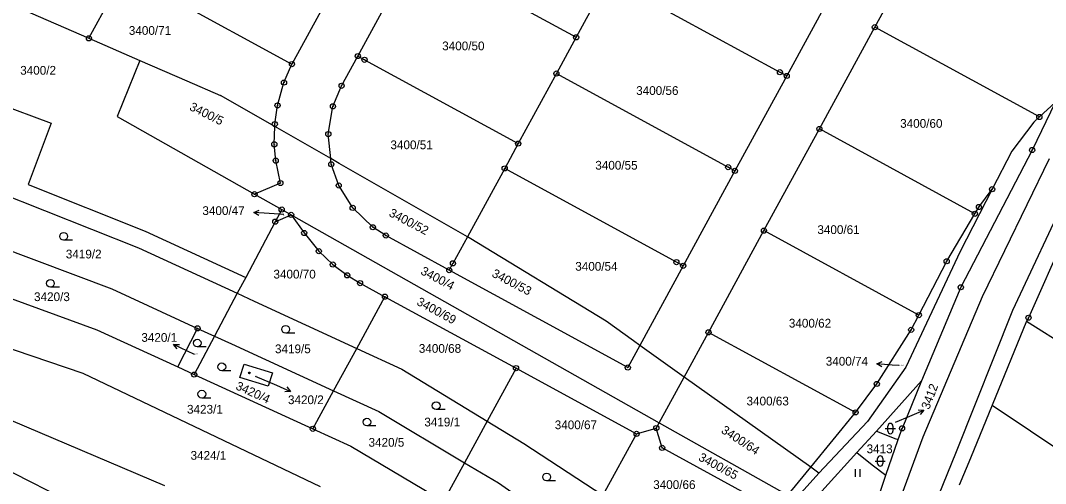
# Model space of a CAD drawing. Extents: x -593183 to -588034, y -1130415 to -1124994.
# Drawn here: x -592529.4 to -592330.3, y -1128767.8 to -1128677.9 of the extents above; entities that cross this region are included whole.
import ezdxf

# ---------------------------------------------------------------- set-up
doc = ezdxf.new("R2010")
doc.units = 0
for name, color, linetype in [('Vrstva 1', 7, 'Continuous'), ('Vrstva 16', 7, 'Continuous'), ('Vrstva 18', 7, 'Continuous'), ('Vrstva 19', 7, 'Continuous'), ('Vrstva 24', 7, 'Continuous'), ('Vrstva 25', 7, 'Continuous'), ('Vrstva 4', 7, 'Continuous')]:
    doc.layers.add(name, color=color, linetype=linetype)

msp = doc.modelspace()

# ---------------------------------------------------------------- linework, layer by layer
at = {"layer": 'Vrstva 1'}
for p, q in [((-592463.89, -1128684.8), (-592452.63, -1128664.17)), ((-592451.32, -1128664.89), (-592421.47, -1128681.16)), ((-592363.45, -1128679.2), (-592355.69, -1128664.97)), ((-592516.11, -1128681.35), (-592509.18, -1128668.65)), ((-592509.18, -1128668.65), (-592476.68, -1128686.37)), ((-592415.24, -1128669.75), (-592421.47, -1128681.16)), ((-592415.24, -1128669.75), (-592381.88, -1128687.94)), ((-592370.51, -1128670.22), (-592380.56, -1128688.66)), ((-592537.4, -1128672.05), (-592516.11, -1128681.35)), ((-592374.22, -1128698.95), (-592363.45, -1128679.2)), ((-592331.49, -1128696.63), (-592363.45, -1128679.2)), ((-592516.11, -1128681.35), (-592506.23, -1128685.64)), ((-592421.47, -1128681.16), (-592425.3, -1128688.19)), ((-592506.23, -1128685.64), (-592509.5, -1128693.81)), ((-592506.23, -1128685.64), (-592497.07, -1128689.63)), ((-592463.89, -1128684.8), (-592462.57, -1128685.52)), ((-592462.57, -1128685.52), (-592432.72, -1128701.8)), ((-592425.3, -1128688.19), (-592432.72, -1128701.8)), ((-592425.3, -1128688.19), (-592391.93, -1128706.38)), ((-592380.56, -1128688.66), (-592390.62, -1128707.1)), ((-592380.56, -1128688.66), (-592381.88, -1128687.94)), ((-592497.07, -1128689.63), (-592490.56, -1128692.47)), ((-592538.73, -1128692.12), (-592523.45, -1128697.86)), ((-592480.01, -1128698.5), (-592490.56, -1128692.47)), ((-592509.5, -1128693.81), (-592510.61, -1128696.56)), ((-592328.41, -1128693.84), (-592332.9, -1128703.05)), ((-592328.41, -1128693.84), (-592331.49, -1128696.63)), ((-592510.61, -1128696.56), (-592483.96, -1128711.63)), ((-592331.49, -1128696.63), (-592332.58, -1128697.62)), ((-592523.45, -1128697.86), (-592527.9, -1128709.77)), ((-592469.15, -1128704.72), (-592480.01, -1128698.5)), ((-592332.58, -1128697.62), (-592336.85, -1128703.28)), ((-592384.99, -1128718.71), (-592374.22, -1128698.95)), ((-592344.02, -1128715.43), (-592374.22, -1128698.95)), ((-592432.72, -1128701.8), (-592435.35, -1128706.62)), ((-592332.9, -1128703.05), (-592346.75, -1128729.7)), ((-592336.85, -1128703.28), (-592340.66, -1128710.66)), ((-592467.5, -1128705.66), (-592469.15, -1128704.72)), ((-592442.59, -1128719.9), (-592467.5, -1128705.66)), ((-592435.35, -1128706.62), (-592442.59, -1128719.9)), ((-592401.99, -1128724.82), (-592435.35, -1128706.62)), ((-592390.62, -1128707.1), (-592391.93, -1128706.38)), ((-592390.62, -1128707.1), (-592400.67, -1128725.53)), ((-592539.83, -1128708.8), (-592506.46, -1128722.05)), ((-592527.9, -1128709.77), (-592505.17, -1128718.8)), ((-592478.92, -1128709.47), (-592483.96, -1128711.63)), ((-592340.66, -1128710.66), (-592346.9, -1128722.74)), ((-592343.23, -1128714.12), (-592340.66, -1128710.66)), ((-592562.55, -1128710.89), (-592511.66, -1128730)), ((-592483.96, -1128711.63), (-592478.67, -1128714.61)), ((-592478.67, -1128714.61), (-592479.92, -1128716.97)), ((-592478.67, -1128714.61), (-592476.83, -1128715.65)), ((-592344.02, -1128715.43), (-592343.23, -1128714.12)), ((-592479.92, -1128716.97), (-592476.83, -1128715.65)), ((-592476.83, -1128715.65), (-592405.33, -1128756.01)), ((-592479.92, -1128716.97), (-592485.65, -1128727.79)), ((-592567.7, -1128718.67), (-592514.6, -1128737.95)), ((-592505.17, -1128718.8), (-592485.65, -1128727.79)), ((-592442.59, -1128719.9), (-592445.4, -1128725.06)), ((-592442.26, -1128720.09), (-592442.59, -1128719.9)), ((-592415.67, -1128736.3), (-592442.26, -1128720.09)), ((-592395.76, -1128738.46), (-592384.99, -1128718.71)), ((-592354.91, -1128735.11), (-592384.99, -1128718.71)), ((-592326.42, -1128719.46), (-592333.6, -1128735.62)), ((-592506.46, -1128722.05), (-592487.29, -1128730.87)), ((-592346.9, -1128722.74), (-592357.41, -1128745.24)), ((-592446.12, -1128726.38), (-592445.4, -1128725.06)), ((-592411.44, -1128745.29), (-592446.12, -1128726.38)), ((-592400.67, -1128725.53), (-592409.1, -1128740.99)), ((-592400.67, -1128725.53), (-592401.99, -1128724.82)), ((-592573.65, -1128727.2), (-592517.32, -1128746.38)), ((-592485.65, -1128727.79), (-592487.29, -1128730.87)), ((-592511.66, -1128730), (-592495, -1128737.68)), ((-592346.75, -1128729.7), (-592354.39, -1128747.86)), ((-592487.29, -1128730.87), (-592491.7, -1128739.2)), ((-592487.29, -1128730.87), (-592483.99, -1128732.38)), ((-592483.99, -1128732.38), (-592464.09, -1128741.57)), ((-592464.09, -1128741.57), (-592458.61, -1128731.53)), ((-592458.61, -1128731.53), (-592433.15, -1128745.41)), ((-592410.33, -1128740.11), (-592415.67, -1128736.3)), ((-592333.99, -1128736.29), (-592340.66, -1128752.59)), ((-592333.6, -1128735.62), (-592333.99, -1128736.29)), ((-592333.99, -1128736.29), (-592315.35, -1128748.08)), ((-592514.6, -1128737.95), (-592498.87, -1128745.18)), ((-592498.87, -1128745.18), (-592495, -1128737.68)), ((-592495, -1128737.68), (-592491.7, -1128739.2)), ((-592400.49, -1128747.13), (-592395.76, -1128738.46)), ((-592367.18, -1128754), (-592395.76, -1128738.46)), ((-592491.7, -1128739.2), (-592495.66, -1128746.66)), ((-592491.7, -1128739.2), (-592488.4, -1128740.7)), ((-592409.1, -1128740.99), (-592410.33, -1128740.11)), ((-592488.4, -1128740.7), (-592468.59, -1128749.82)), ((-592468.59, -1128749.82), (-592464.09, -1128741.57)), ((-592464.09, -1128741.57), (-592455.3, -1128745.62)), ((-592409.1, -1128740.99), (-592411.44, -1128745.29)), ((-592400.49, -1128747.13), (-592409.1, -1128740.99)), ((-592517.32, -1128746.38), (-592471.18, -1128768.42)), ((-592498.87, -1128745.18), (-592495.66, -1128746.66)), ((-592486.78, -1128747.21), (-592485.97, -1128744.61)), ((-592485.97, -1128744.61), (-592480.48, -1128746.32)), ((-592480.48, -1128746.32), (-592481.29, -1128748.92)), ((-592455.3, -1128745.62), (-592438.76, -1128755.69)), ((-592433.15, -1128745.41), (-592438.76, -1128755.69)), ((-592433.15, -1128745.41), (-592409.73, -1128758.18)), ((-592357.41, -1128745.24), (-592364.89, -1128755.79)), ((-592495.66, -1128746.66), (-592472.61, -1128757.19)), ((-592481.29, -1128748.92), (-592486.78, -1128747.21)), ((-592405.33, -1128756.01), (-592400.49, -1128747.13)), ((-592375.91, -1128764.65), (-592400.49, -1128747.13)), ((-592354.39, -1128747.86), (-592363.15, -1128757.65)), ((-592354.39, -1128747.86), (-592358.16, -1128757.1)), ((-592472.61, -1128757.19), (-592468.59, -1128749.82)), ((-592468.59, -1128749.82), (-592459.78, -1128753.86)), ((-592542.34, -1128750.84), (-592501.44, -1128768.19)), ((-592459.78, -1128753.86), (-592443.17, -1128763.78)), ((-592375.91, -1128764.65), (-592367.18, -1128754)), ((-592340.66, -1128752.59), (-592344.88, -1128762.87)), ((-592340.66, -1128752.59), (-592318.82, -1128767.24)), ((-592438.76, -1128755.69), (-592443.17, -1128763.78)), ((-592438.76, -1128755.69), (-592431.6, -1128760.04)), ((-592405.9, -1128757.05), (-592405.33, -1128756.01)), ((-592405.33, -1128756.01), (-592380.91, -1128769.78)), ((-592364.89, -1128755.79), (-592374.32, -1128765.79)), ((-592472.61, -1128757.19), (-592465.21, -1128760.57)), ((-592409.73, -1128758.18), (-592416.3, -1128770.05)), ((-592409.73, -1128758.18), (-592405.9, -1128757.05)), ((-592404.77, -1128760.89), (-592405.9, -1128757.05)), ((-592363.15, -1128757.65), (-592366.94, -1128761.82)), ((-592363.15, -1128757.65), (-592359.39, -1128759.11)), ((-592358.92, -1128759.29), (-592358.16, -1128757.1)), ((-592431.6, -1128760.04), (-592416.3, -1128770.05)), ((-592361.31, -1128766.22), (-592358.92, -1128759.29)), ((-592359.39, -1128759.11), (-592358.92, -1128759.29)), ((-592539.2, -1128761.5), (-592512.55, -1128775)), ((-592465.21, -1128760.57), (-592447.25, -1128771.27)), ((-592383.4, -1128772.54), (-592404.77, -1128760.89)), ((-592366.94, -1128761.82), (-592373.75, -1128769.33)), ((-592366.94, -1128761.82), (-592363.95, -1128764.16)), ((-592443.17, -1128763.78), (-592447.25, -1128771.27)), ((-592443.17, -1128763.78), (-592436.57, -1128767.71)), ((-592363.95, -1128764.16), (-592361.31, -1128766.22)), ((-592344.88, -1128762.87), (-592347.06, -1128768.15)), ((-592374.32, -1128765.79), (-592378.94, -1128770.89)), ((-592374.32, -1128765.79), (-592375.91, -1128764.65)), ((-592364.49, -1128775.42), (-592361.31, -1128766.22)), ((-592436.57, -1128767.71), (-592420.95, -1128778.46))]:
    msp.add_line(p, q, dxfattribs=at)
for points in [[(-592498.65, -1128649.33), (-592469.67, -1128665.13), (-592468.08, -1128670.56), (-592476.68, -1128686.37)], [(-592480.01, -1128698.5), (-592480, -1128698.01), (-592479.47, -1128694.38), (-592478.22, -1128689.95), (-592476.68, -1128686.37)], [(-592469.15, -1128704.72), (-592469.61, -1128699.96), (-592468.71, -1128694.57), (-592467.03, -1128690.58), (-592463.89, -1128684.8)], [(-592478.92, -1128709.47), (-592479.83, -1128705.11), (-592480.1, -1128701.94), (-592480.01, -1128698.5)], [(-592446.12, -1128726.38), (-592458.45, -1128719.65), (-592460.96, -1128718.05), (-592464.88, -1128714.28), (-592467.59, -1128709.94), (-592469.04, -1128705.82), (-592469.15, -1128704.72)], [(-592476.83, -1128715.65), (-592474.3, -1128719.16), (-592471.46, -1128722.69), (-592468.72, -1128725.29), (-592465.93, -1128727.38), (-592463.44, -1128728.9), (-592458.61, -1128731.53)], [(-592354.91, -1128735.11), (-592349.49, -1128724.65), (-592344.02, -1128715.43)], [(-592367.18, -1128754), (-592363.07, -1128748.48), (-592356.39, -1128737.97), (-592354.91, -1128735.11)], [(-592382.73, -1128772.9), (-592379.79, -1128769.38), (-592375.91, -1128764.65)]]:
    msp.add_lwpolyline(points, dxfattribs=at)
at = {"layer": 'Vrstva 16'}
for p, q in [((-592478.28, -1128715.55), (-592481.11, -1128715.37)), ((-592495.63, -1128742.76), (-592496.96, -1128742.11)), ((-592358.77, -1128744.91), (-592360.07, -1128744.8)), ((-592483.8, -1128746.94), (-592479.68, -1128748.73)), ((-592359.42, -1128755.93), (-592356.67, -1128754.75))]:
    msp.add_line(p, q, dxfattribs=at)
at = {"layer": 'Vrstva 24'}
for centre, radius in [((-592363.45, -1128679.2), 0.5), ((-592421.47, -1128681.16), 0.5), ((-592363.45, -1128679.2), 0.0327), ((-592516.11, -1128681.35), 0.5), ((-592516.11, -1128681.35), 0.0327), ((-592421.47, -1128681.16), 0.0327), ((-592463.89, -1128684.8), 0.5), ((-592463.89, -1128684.8), 0.0327), ((-592476.68, -1128686.37), 0.5), ((-592476.68, -1128686.37), 0.0327), ((-592462.57, -1128685.52), 0.5), ((-592462.57, -1128685.52), 0.0327), ((-592425.3, -1128688.19), 0.5), ((-592425.3, -1128688.19), 0.0327), ((-592381.88, -1128687.94), 0.5), ((-592381.88, -1128687.94), 0.0327), ((-592380.56, -1128688.66), 0.5), ((-592380.56, -1128688.66), 0.0327), ((-592478.22, -1128689.95), 0.5), ((-592478.22, -1128689.95), 0.0327), ((-592467.03, -1128690.58), 0.5), ((-592467.03, -1128690.58), 0.0327), ((-592479.47, -1128694.38), 0.5), ((-592479.47, -1128694.38), 0.0327), ((-592468.71, -1128694.57), 0.5), ((-592468.71, -1128694.57), 0.0327), ((-592331.49, -1128696.63), 0.5), ((-592331.49, -1128696.63), 0.0327), ((-592480, -1128698.01), 0.5), ((-592480, -1128698.01), 0.0327), ((-592374.22, -1128698.95), 0.5), ((-592469.61, -1128699.96), 0.5), ((-592469.61, -1128699.96), 0.0327), ((-592374.22, -1128698.95), 0.0327), ((-592480.1, -1128701.94), 0.5), ((-592480.1, -1128701.94), 0.0327), ((-592432.72, -1128701.8), 0.5), ((-592432.72, -1128701.8), 0.0327), ((-592332.9, -1128703.05), 0.5), ((-592479.83, -1128705.11), 0.5), ((-592332.9, -1128703.05), 0.0327), ((-592479.83, -1128705.11), 0.0327), ((-592469.04, -1128705.82), 0.5), ((-592469.04, -1128705.82), 0.0327), ((-592435.35, -1128706.62), 0.5), ((-592435.35, -1128706.62), 0.0327), ((-592391.93, -1128706.38), 0.5), ((-592391.93, -1128706.38), 0.0327), ((-592390.62, -1128707.1), 0.5), ((-592390.62, -1128707.1), 0.0327), ((-592478.92, -1128709.47), 0.5), ((-592478.92, -1128709.47), 0.0327), ((-592467.59, -1128709.94), 0.5), ((-592467.59, -1128709.94), 0.0327), ((-592340.66, -1128710.66), 0.5), ((-592340.66, -1128710.66), 0.0327), ((-592483.96, -1128711.63), 0.5), ((-592483.96, -1128711.63), 0.0327), ((-592478.67, -1128714.61), 0.5), ((-592478.67, -1128714.61), 0.0327), ((-592464.88, -1128714.28), 0.5), ((-592464.88, -1128714.28), 0.0327), ((-592343.23, -1128714.12), 0.5), ((-592343.23, -1128714.12), 0.0327), ((-592479.92, -1128716.97), 0.5), ((-592476.83, -1128715.65), 0.5), ((-592476.83, -1128715.65), 0.0327), ((-592344.02, -1128715.43), 0.5), ((-592344.02, -1128715.43), 0.0327), ((-592479.92, -1128716.97), 0.0327), ((-592460.96, -1128718.05), 0.5), ((-592460.96, -1128718.05), 0.0327), ((-592384.99, -1128718.71), 0.5), ((-592474.3, -1128719.16), 0.5), ((-592474.3, -1128719.16), 0.0327), ((-592458.45, -1128719.65), 0.5), ((-592458.45, -1128719.65), 0.0327), ((-592384.99, -1128718.71), 0.0327), ((-592471.46, -1128722.69), 0.5), ((-592471.46, -1128722.69), 0.0327), ((-592445.4, -1128725.06), 0.5), ((-592401.99, -1128724.82), 0.5), ((-592349.49, -1128724.65), 0.5), ((-592468.72, -1128725.29), 0.5), ((-592468.72, -1128725.29), 0.0327), ((-592446.12, -1128726.38), 0.5), ((-592446.12, -1128726.38), 0.0327), ((-592445.4, -1128725.06), 0.0327), ((-592401.99, -1128724.82), 0.0327), ((-592400.67, -1128725.53), 0.5), ((-592400.67, -1128725.53), 0.0327), ((-592349.49, -1128724.65), 0.0327), ((-592465.93, -1128727.38), 0.5), ((-592465.93, -1128727.38), 0.0327), ((-592463.44, -1128728.9), 0.5), ((-592463.44, -1128728.9), 0.0327), ((-592346.75, -1128729.7), 0.5), ((-592346.75, -1128729.7), 0.0327), ((-592458.61, -1128731.53), 0.5), ((-592458.61, -1128731.53), 0.0327), ((-592354.91, -1128735.11), 0.5), ((-592354.91, -1128735.11), 0.0327), ((-592333.6, -1128735.62), 0.5), ((-592333.6, -1128735.62), 0.0327), ((-592495, -1128737.68), 0.5), ((-592495, -1128737.68), 0.0327), ((-592395.76, -1128738.46), 0.5), ((-592395.76, -1128738.46), 0.0327), ((-592356.39, -1128737.97), 0.5), ((-592356.39, -1128737.97), 0.0327), ((-592495.66, -1128746.66), 0.5), ((-592433.15, -1128745.41), 0.5), ((-592433.15, -1128745.41), 0.0327), ((-592411.44, -1128745.29), 0.5), ((-592411.44, -1128745.29), 0.0327), ((-592495.66, -1128746.66), 0.0327), ((-592363.07, -1128748.48), 0.5), ((-592363.07, -1128748.48), 0.0327), ((-592367.18, -1128754), 0.5), ((-592367.18, -1128754), 0.0327), ((-592472.61, -1128757.19), 0.5), ((-592472.61, -1128757.19), 0.0327), ((-592409.73, -1128758.18), 0.5), ((-592409.73, -1128758.18), 0.0327), ((-592405.9, -1128757.05), 0.5), ((-592405.9, -1128757.05), 0.0327), ((-592358.16, -1128757.1), 0.5), ((-592358.16, -1128757.1), 0.0327), ((-592404.77, -1128760.89), 0.5), ((-592404.77, -1128760.89), 0.0327)]:
    msp.add_circle(centre, radius, dxfattribs=at)
at = {"layer": 'Vrstva 25'}
for p, q in [((-592481.11, -1128715.37), (-592484.1, -1128715.18)), ((-592519.28, -1128720.57), (-592521.03, -1128720.57)), ((-592521.84, -1128729.69), (-592523.59, -1128729.69)), ((-592476.14, -1128738.62), (-592477.89, -1128738.62)), ((-592496.96, -1128742.11), (-592499.66, -1128740.8)), ((-592493.32, -1128741.29), (-592495.07, -1128741.29)), ((-592488.55, -1128745.91), (-592490.3, -1128745.91)), ((-592360.07, -1128744.8), (-592363.06, -1128744.55)), ((-592479.68, -1128748.73), (-592476.93, -1128749.93)), ((-592492.43, -1128751.21), (-592494.18, -1128751.21)), ((-592446.91, -1128753.45), (-592448.66, -1128753.45)), ((-592356.67, -1128754.75), (-592353.91, -1128753.57)), ((-592460.36, -1128756.64), (-592462.11, -1128756.64)), ((-592361.43, -1128757.15), (-592359.43, -1128757.15)), ((-592360.93, -1128757.65), (-592360.93, -1128756.65)), ((-592359.93, -1128756.65), (-592359.93, -1128757.65)), ((-592363.41, -1128763.45), (-592361.41, -1128763.45)), ((-592362.91, -1128763.95), (-592362.91, -1128762.95)), ((-592361.91, -1128762.95), (-592361.91, -1128763.95)), ((-592367.29, -1128765.04), (-592367.29, -1128766.54)), ((-592366.27, -1128766.54), (-592366.27, -1128765.04)), ((-592425.45, -1128767.3), (-592427.2, -1128767.3))]:
    msp.add_line(p, q, dxfattribs=at)
for points in [[(-592483.14, -1128715.74), (-592484.1, -1128715.18), (-592483.07, -1128714.74)], [(-592498.98, -1128741.68), (-592499.66, -1128740.8), (-592498.54, -1128740.79)], [(-592362.11, -1128745.13), (-592363.06, -1128744.55), (-592362.02, -1128744.13)], [(-592477.65, -1128749.07), (-592476.93, -1128749.93), (-592478.05, -1128749.99)], [(-592355.03, -1128753.5), (-592353.91, -1128753.57), (-592354.63, -1128754.42)]]:
    msp.add_lwpolyline(points, dxfattribs=at)
for centre, radius in [((-592521.03, -1128719.82), 0.75), ((-592523.59, -1128728.94), 0.75), ((-592477.89, -1128737.87), 0.75), ((-592495.07, -1128740.54), 0.75), ((-592490.3, -1128745.16), 0.75), ((-592484.95, -1128746.34), 0.175), ((-592484.95, -1128746.34), 0.15), ((-592494.18, -1128750.46), 0.75), ((-592448.66, -1128752.7), 0.75), ((-592462.11, -1128755.89), 0.75), ((-592427.2, -1128766.55), 0.75)]:
    msp.add_circle(centre, radius, dxfattribs=at)
for centre, start, end in [((-592360.43, -1128756.65), 90, 180), ((-592360.43, -1128756.65), 0, 90), ((-592360.43, -1128757.65), 180, 270), ((-592360.43, -1128757.65), 270, 0), ((-592362.41, -1128762.95), 90, 180), ((-592362.41, -1128763.95), 180, 270), ((-592362.41, -1128762.95), 0, 90), ((-592362.41, -1128763.95), 270, 0)]:
    msp.add_arc(centre, 0.5, start, end, dxfattribs=at)
at = {"layer": 'Vrstva 4'}
for p, q in [((-592329.61, -1128704.73), (-592342.61, -1128731.57)), ((-592324.18, -1128707.5), (-592336.73, -1128734.21)), ((-592342.61, -1128731.57), (-592354.15, -1128758.84)), ((-592336.73, -1128734.21), (-592347.67, -1128761.66)), ((-592354.15, -1128758.84), (-592364.52, -1128786.87)), ((-592347.67, -1128761.66), (-592358.89, -1128789.2))]:
    msp.add_line(p, q, dxfattribs=at)

# ---------------------------------------------------------------- texts
at = {"layer": 'Vrstva 16'}
for s, p in [('3400/47', (-592494.07, -1128715.67)), ('3420/1', (-592505.93, -1128740.3)), ('3400/74', (-592372.98, -1128744.92)), ('3420/2', (-592477.45, -1128752.4))]:
    msp.add_text(s, height=1.7, dxfattribs=at).set_placement(p)
msp.add_text('3412', height=1.7, rotation=69.1349, dxfattribs=at).set_placement((-592352.91, -1128753.57))
at = {"layer": 'Vrstva 18'}
for s, height, p in [('3400/71', 1.7, (-592508.36, -1128680.68)), ('3400/50', 1.7, (-592447.49, -1128683.68)), ('3400/2', 1.7, (-592529.46, -1128688.42)), ('3400/56', 1.7, (-592409.81, -1128692.35)), ('3400/60', 1.7, (-592358.53, -1128698.73)), ('3400/51', 1.7, (-592457.54, -1128702.89)), ('3400/55', 1.7, (-592417.75, -1128706.86)), ('3400/47', 0.2, (-592478.75, -1128715.8)), ('3400/61', 1.7, (-592374.61, -1128719.36)), ('3419/2', 1.7, (-592520.6, -1128724.1)), ('3400/70', 1.7, (-592480.27, -1128728)), ('3400/54', 1.7, (-592421.64, -1128726.49)), ('3420/3', 1.7, (-592526.77, -1128732.39)), ('3400/62', 1.7, (-592380.15, -1128737.53)), ('3419/5', 1.7, (-592479.97, -1128742.51)), ('3400/68', 1.7, (-592452.03, -1128742.43)), ('3420/1', 0.2, (-592495.63, -1128742.76)), ('3400/74', 0.2, (-592358.77, -1128744.91)), ('3423/1', 1.7, (-592497.06, -1128754.25)), ('3400/63', 1.7, (-592388.37, -1128752.65)), ('3419/1', 1.7, (-592450.96, -1128756.73)), ('3400/67', 1.7, (-592425.63, -1128757.27)), ('3412', 0.1, (-592359.42, -1128755.93)), ('3420/5', 1.7, (-592461.8, -1128760.67)), ('3413', 1.7, (-592365.05, -1128761.93)), ('3424/1', 1.7, (-592496.37, -1128763.2)), ('3400/66', 1.7, (-592406.5, -1128768.88))]:
    msp.add_text(s, height=height, dxfattribs=at).set_placement(p)
for s, rotation, p in [('3400/5', 333.5242, (-592496.73, -1128695.2)), ('3400/52', 332.3144, (-592457.98, -1128715.79)), ('3400/4', 332.1895, (-592451.83, -1128727.07)), ('3400/53', 332.4386, (-592437.99, -1128727.55)), ('3400/69', 331.5839, (-592452.59, -1128733.03)), ('3420/4', 335.4401, (-592487.75, -1128749.45)), ('3400/64', 326.8215, (-592393.44, -1128757.85)), ('3400/65', 331.742, (-592397.85, -1128763.23))]:
    msp.add_text(s, height=1.7, rotation=rotation, dxfattribs=at).set_placement(p)
at = {"layer": 'Vrstva 19'}
msp.add_text('3420/2', height=0.1, dxfattribs=at).set_placement((-592483.8, -1128746.94))

doc.saveas('drawing.dxf')
